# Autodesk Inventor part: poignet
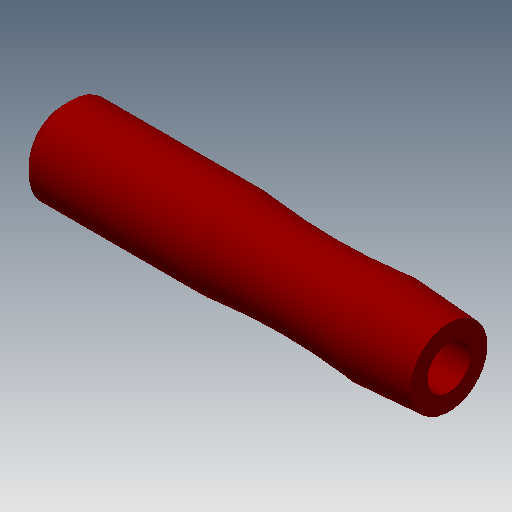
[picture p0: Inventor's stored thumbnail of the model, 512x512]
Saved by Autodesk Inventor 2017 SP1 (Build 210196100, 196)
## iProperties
Shininess: 64.0
Length Units: 11269
Angle Units: 11279
Time Units: 11290
Mass Units: 11283
Length Display Precision: 3
Angle Display Precision: 2
Compacted: True
Part Number: poignet
Document SubType Name: Modeling
Created: 2003-07
Material: Générique
Designer: trameau
Density: 1 g/cm^3
Appearance: Rouge (opaque)
Mass: 25.4291 g
Surface Area: 62.8468 cm^2
Volume: 25.4291 cm^3
Density: 0.0
Volumn: 0.0
Area: 0.0
PropertySet Name: Model Information
Control State: 0
Master: False
Checked Out: False
Author: trameau
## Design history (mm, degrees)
sketch "Esquisse1"
  geometry: L1 (-45.193, 3.01)-(-45.193, 11.01); L2 (-43.193, 13.01)-(-5.193, 13.01); L3 (-5.193, 13.01)-(-5.193, 12.01); L4 (-5.193, 12.01)-(29.807, 12.01); L5 (29.807, 12.01)-(29.807, 13.01); L6 (29.807, 13.01)-(29.807, 13.01); L7 (29.807, 13.01)-(44.807, 12.01); L8 (44.807, 12.01)-(44.807, 3.01); L9 (44.807, 3.01)-(-45.193, 3.01); L10 (-43.193, 13.01)-(-45.193, 11.01); A1 r 153.625 centre (12.307, 165.635) between (-5.193, 13.01) and (29.807, 13.01); 1 further point
  constraints: 20 end point, 5 parallel, 2 point on circle, 2 point on line, 1 centre point, 1 collinear, 1 perpendicular, 1 tangent, 1 vertical
  dimensions: "d1" = 90 distance between parallel lines of L1 L8; "d2" = 40 distance of point (-45.193, 13.01) L2.end; "d3" = 18 diameter of L4 L9; "d4" = 20 diameter of L2 L9; "d5" = 18 diameter of L7.end L9 (= d3); "d6" = 20 diameter of L6 L9; "d7" = 15 distance from line of L6.end L8; "d8" = 35 distance of L3.end L4.end; "d9" = 2 distance of L2.start point (-45.193, 13.01); "d10" = 2 distance of L1.end point (-45.193, 13.01) (= d9)
revolve "Révolution1" sketch "Esquisse1" stored, may be unused: angle "d11" = 90 deg
sketch "Esquisse2"
  geometry: C1 r 9 at (0, 0) reference
hole "Perçage1" sketch "Esquisse2" at (0, 0) diameter "d12" = 10; stored, may be unused: countersink angle "d16" = 82 deg, drill point angle "d18" = 118 deg; dims "d13" = 6, "d14" = 4, "d15" = 2, "d17" = 10
node "Solide1"
node "Corps solides"
node "Corps surfaciques"
